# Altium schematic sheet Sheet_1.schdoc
size 279 x 210 mm
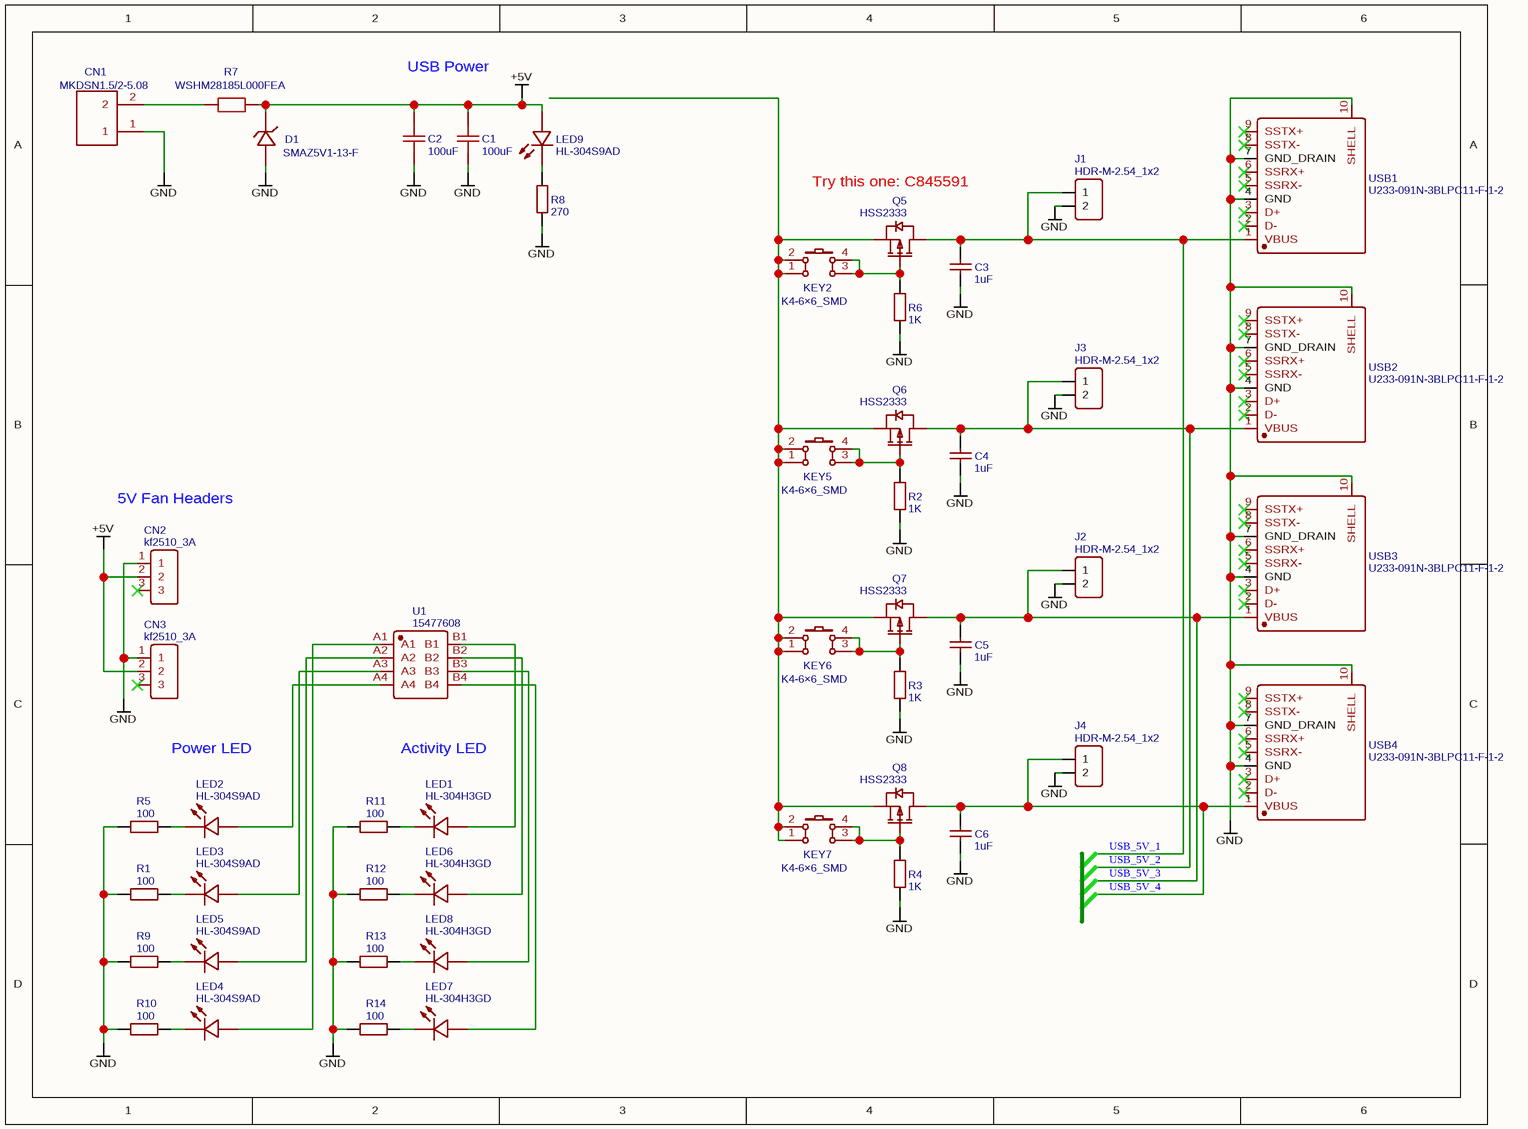
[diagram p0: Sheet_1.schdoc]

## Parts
C1  100uF  [C1210]
C2  100uF  [C1210]
C3  1uF  [C1206]
C4  1uF  [C1206]
C5  1uF  [C1206]
C6  1uF  [C1206]
CN1  MKDSN1.5/2-5.08  [CONN-TH_2P-P5.08_1714984]
CN2  kf2510_3A  [CONN-TH_3P-P2.00_KF2510_3A]
CN3  kf2510_3A  [CONN-TH_3P-P2.00_KF2510_3A]
D1  SMAZ5V1-13-F  [SMA_L4.3-W2.6-LS5.2-RD]
J1  HDR-M-2.54_1x2  [HDR-M-2.54_1X2]
J2  HDR-M-2.54_1x2  [HDR-M-2.54_1X2]
J3  HDR-M-2.54_1x2  [HDR-M-2.54_1X2]
J4  HDR-M-2.54_1x2  [HDR-M-2.54_1X2]
KEY2  K4-6×6_SMD  [KEY-SMD_4P-L6.0-W6.0-P3.90-LS10.0]
KEY5  K4-6×6_SMD  [KEY-SMD_4P-L6.0-W6.0-P3.90-LS10.0]
KEY6  K4-6×6_SMD  [KEY-SMD_4P-L6.0-W6.0-P3.90-LS10.0]
KEY7  K4-6×6_SMD  [KEY-SMD_4P-L6.0-W6.0-P3.90-LS10.0]
LED1  HL-304H3GD  [LED-TH_BD3.0-P2.54-FD]
LED2  HL-304S9AD  [LED-TH_BD3.0-P2.54-FD]
LED3  HL-304S9AD  [LED-TH_BD3.0-P2.54-FD]
LED4  HL-304S9AD  [LED-TH_BD3.0-P2.54-FD]
LED5  HL-304S9AD  [LED-TH_BD3.0-P2.54-FD]
LED6  HL-304H3GD  [LED-TH_BD3.0-P2.54-FD]
LED7  HL-304H3GD  [LED-TH_BD3.0-P2.54-FD]
LED8  HL-304H3GD  [LED-TH_BD3.0-P2.54-FD]
LED9  HL-304S9AD  [LED-TH_BD3.0-P2.54-FD]
Q5  HSS2333  [SOT-23-3_L2.9-W1.3-P1.90-LS2.4-BR]
Q6  HSS2333  [SOT-23-3_L2.9-W1.3-P1.90-LS2.4-BR]
Q7  HSS2333  [SOT-23-3_L2.9-W1.3-P1.90-LS2.4-BR]
Q8  HSS2333  [SOT-23-3_L2.9-W1.3-P1.90-LS2.4-BR]
R1  100  [R1206]
R2  1K  [R1206]
R3  1K  [R1206]
R4  1K  [R1206]
R5  100  [R1206]
R6  1K  [R1206]
R7  WSHM28185L000FEA  [R2818]
R8  270  [R1206]
R9  100  [R1206]
R10  100  [R1206]
R11  100  [R1206]
R12  100  [R1206]
R13  100  [R1206]
R14  100  [R1206]
U1  15477608  [CONN-TH_8P-P2.54-V-M_15477608]
USB1  U233-091N-3BLPC11-F-1-2  [USB3.0-A-TH_U233-091N-1BLPC15-S-1-2]
USB2  U233-091N-3BLPC11-F-1-2  [USB3.0-A-TH_U233-091N-1BLPC15-S-1-2]
USB3  U233-091N-3BLPC11-F-1-2  [USB3.0-A-TH_U233-091N-1BLPC15-S-1-2]
USB4  U233-091N-3BLPC11-F-1-2  [USB3.0-A-TH_U233-091N-1BLPC15-S-1-2]

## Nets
+5V: C1.2 C2.2 CN2.2 CN3.2 D1.1(C) LED9.2(A) R7.2
GND: C1.1 C2.1 C3.1 C4.1 C5.1 C6.1 CN1.1 CN2.1 CN3.1 D1.2(A) J1.2 J2.2 J3.2 J4.2 R1.1 R2.1 R3.1 R4.1 R5.1 R6.1 R8.1 R9.1 R10.1 R11.1 R12.1 R13.1 R14.1 USB1.4(GND) USB1.7(GND_DRAIN) USB1.10(SHELL) USB2.4(GND) USB2.7(GND_DRAIN) USB2.10(SHELL) USB3.4(GND) USB3.7(GND_DRAIN) USB3.10(SHELL) USB4.4(GND) USB4.7(GND_DRAIN) USB4.10(SHELL)
USB_5V_1: C3.2 J1.1 Q5.3(D) USB1.1(VBUS)
USB_5V_2: C4.2 J3.1 Q6.3(D) USB2.1(VBUS)
USB_5V_3: C5.2 J2.1 Q7.3(D) USB3.1(VBUS)
USB_5V_4: C6.2 J4.1 Q8.3(D) USB4.1(VBUS)
NetCN1_2: CN1.2 R7.1
NetKEY2_1: KEY2.1 KEY2.2 KEY5.1 KEY5.2 KEY6.1 KEY6.2 KEY7.1 KEY7.2 Q5.2(S) Q6.2(S) Q7.2(S) Q8.2(S)
NetKEY2_3: KEY2.3 KEY2.4 Q5.1(G) R6.2
NetKEY5_3: KEY5.3 KEY5.4 Q6.1(G) R2.2
NetKEY6_3: KEY6.3 KEY6.4 Q7.1(G) R3.2
NetKEY7_3: KEY7.3 KEY7.4 Q8.1(G) R4.2
NetLED1_1: LED1.1(C) R11.2
NetLED1_2: LED1.2(A) U1.B1
NetLED2_1: LED2.1(C) R5.2
NetLED2_2: LED2.2(A) U1.A4
NetLED3_1: LED3.1(C) R1.2
NetLED3_2: LED3.2(A) U1.A3
NetLED4_1: LED4.1(C) R10.2
NetLED4_2: LED4.2(A) U1.A1
NetLED5_1: LED5.1(C) R9.2
NetLED5_2: LED5.2(A) U1.A2
NetLED6_1: LED6.1(C) R12.2
NetLED6_2: LED6.2(A) U1.B2
NetLED7_1: LED7.1(C) R14.2
NetLED7_2: LED7.2(A) U1.B4
NetLED8_1: LED8.1(C) R13.2
NetLED8_2: LED8.2(A) U1.B3
NetLED9_1: LED9.1(C) R8.2

Not connected (* = marked no-connect by the designer): CN2 3*; CN3 3*; USB1 2(D-)* 3(D+)* 5(SSRX-)* 6(SSRX+)* 8(SSTX-)* 9(SSTX+)*; USB2 2(D-)* 3(D+)* 5(SSRX-)* 6(SSRX+)* 8(SSTX-)* 9(SSTX+)*; USB3 2(D-)* 3(D+)* 5(SSRX-)* 6(SSRX+)* 8(SSTX-)* 9(SSTX+)*; USB4 2(D-)* 3(D+)* 5(SSRX-)* 6(SSRX+)* 8(SSTX-)* 9(SSTX+)*

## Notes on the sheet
- USB Power
- Try this one: C845591
- 5V Fan Headers
- Power LED
- Activity LED

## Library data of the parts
C1 C2 = 100uF: BOM_Manufacturer: Taiyo Yuden; BOM_Manufacturer Part: EMK325ABJ107MM-P; nameAlias: Capacitance; Contributor: LCSC; SMT Type: Extend; BOM_Paste Type: expand
C3-C6 = 1uF: BOM_Manufacturer: YAGEO; BOM_Manufacturer Part: CC1206KKX7R8BB105; nameAlias: Capacitance; SMT Type: Extend; BOM_Paste Type: expand
CN1 = MKDSN1.5/2-5.08: BOM_Manufacturer: Phoenix Contact; SMT Type: Extend; BOM_Paste Type: expand
CN2 CN3 = kf2510_3A: BOM_Manufacturer: BOOMELE; SMT Type: Extend; BOM_Paste Type: expand
D1 = SMAZ5V1-13-F: BOM_Manufacturer: DIODES; Contributor: LCSC; SMT Type: Extend; BOM_Paste Type: expand
J1-J4 = HDR-M-2.54_1x2: Contributor: LCEDA_Lib
KEY2 KEY5-KEY7 = K4-6×6_SMD: BOM_Manufacturer: 韩国韩荣; BOM_Manufacturer Part: K2-6639SP-D4SC-04; Contributor: LCEDA_Lib
LED1 LED6-LED8 = HL-304H3GD: BOM_Manufacturer: HONGLITRONIC(Hongli Zhihui (HONGLITRONIC)); Contributor: LCSC; SMT Type: Extend; BOM_Paste Type: expand
LED2-LED5 LED9 = HL-304S9AD: BOM_Manufacturer: HONGLITRONIC(Hongli Zhihui (HONGLITRONIC)); Contributor: LCSC; SMT Type: Extend; BOM_Paste Type: expand
Q5-Q8 = HSS2333: BOM_Manufacturer: HUASHUO; Contributor: LCSC
R1 R5 R9-R14 = 100: BOM_Manufacturer: YAGEO; BOM_Manufacturer Part: RC1206JR-07100RL; nameAlias: Resistance (Ohms); Contributor: LCSC
R2-R4 R6 = 1K: BOM_Manufacturer: YAGEO; BOM_Manufacturer Part: RC1206FR-071KL; nameAlias: Resistance (Ohms)
R7 = WSHM28185L000FEA: BOM_Manufacturer: Vishay Intertech; Contributor: LCSC
R8 = 270: BOM_Manufacturer Part: 1206W4F2700T5E; BOM_Manufacturer: UniOhm; nameAlias: Resistance (Ohms); SMT Type: Extend; BOM_Paste Type: expand
U1 = 15477608: BOM_Manufacturer: MOLEX; Contributor: LCSC; SMT Type: Extend; BOM_Paste Type: expand
USB1-USB4 = U233-091N-3BLPC11-F-1-2: BOM_Manufacturer: XKB Enterprise; Contributor: LCSC; SMT Type: Extend; BOM_Paste Type: expand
